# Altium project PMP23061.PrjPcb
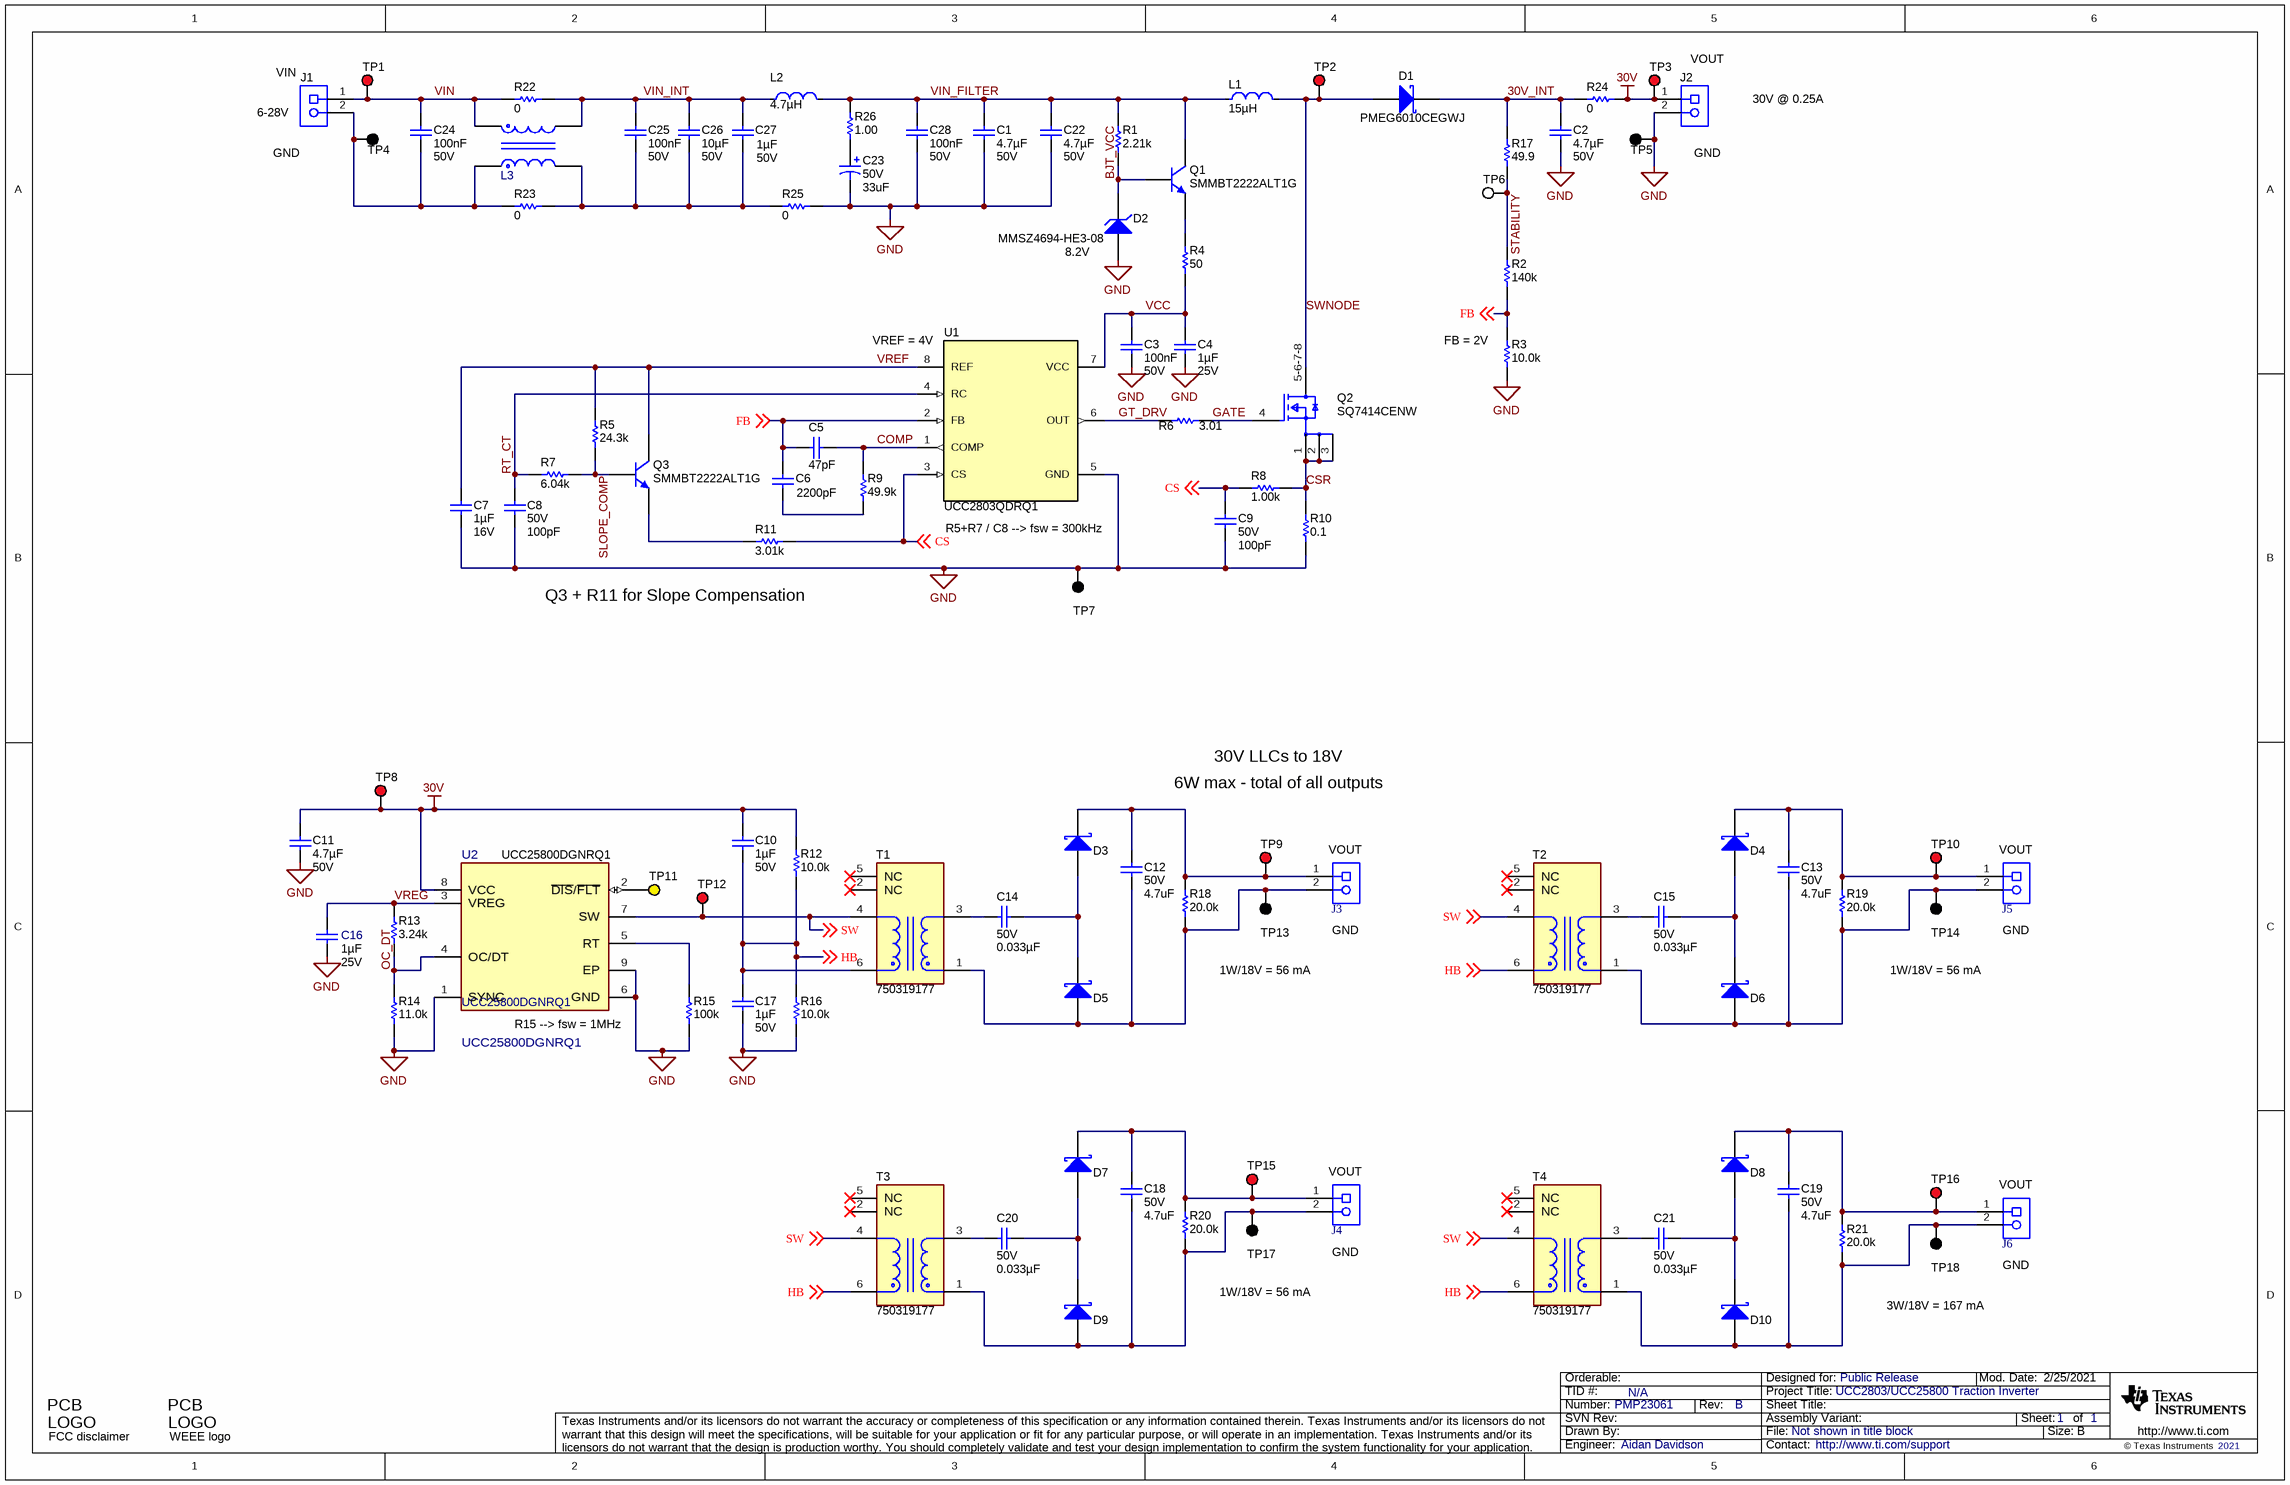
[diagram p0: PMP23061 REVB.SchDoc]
TID: N/A; TechSupport: http://www.ti.com/support; SCH_Rev: B; PRJ_Title: UCC2803/UCC25800 Traction Inverter; PRJ_Number: PMP23061; PRJ_Engineer: Aidan Davidson; PRJ_Customer: Public Release; PCB_Rev: B; PCB_Layout: Aidan Davidson; CopyrightYear: 2021
1 sheet, 102 parts. Net scope: global (net labels, ports and power ports of the same name join across sheets).
Board file: PMP23061 REVB.PcbDoc

## Sheet PMP23061 REVB.SchDoc
size 431 x 279 mm; Date: Not shown in title block; ApprovedBy: Not shown in title block; CheckedBy: Not shown in title block; Author: Not shown in title block; CompanyName: Not shown in title block; Engineer: Not shown in title block; Organization: Not shown in title block; Address1: Not shown in title block; Address2: Not shown in title block; Address3: Not shown in title block; Address4: Not shown in title block; DocumentNumber: 1; Revision: Use project parameter SCH_Rev; SheetNumber: 1; SheetTotal: 1; PageSetup: Record=PageOptions¦CenterHorizontal=True¦CenterVertical=True¦PrintScale=1.00¦XCorrection=1.00¦YCorrection=1.00¦PrintKind=0¦BorderSize=5000000¦LeftOffset=0¦BottomOffset=0¦Orientation=2¦PaperLength=1000¦PaperWidth=1000¦Scale=100¦PaperSource=15¦PrintQuality=600¦MediaType=1¦DitherType=10¦PaperKind=Letter¦PrintScaleMode=1

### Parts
C1  ValueDisplayed: 4.7µF  VDC_V: 50V  [1206_190]  (hidden comment: CGA5L3X7R1H475K160AE)
C2  ValueDisplayed: 4.7µF  VDC_V: 50V  [1206_190]  (hidden comment: CGA5L3X7R1H475K160AE)
C3  Cap_F: 100nF  VDC_V: 50V  [0603]  (hidden comment: CGA3E2X7R1H104K080AA)
C4  Cap_F: 1µF  VDC_V: 25V  [0603]  (hidden comment: GCM188R71E105KA64D)
C5  ValueDisplayed: 47pF  [0402]  (hidden comment: CGA2B2C0G1H470J050BA)
C6  ValueDisplayed: 2200pF  [0402]  (hidden comment: GCM155R71H222KA37D)
C7  Cap_F: 1µF  VDC_V: 16V  [0603]  (hidden comment: GCM188R71C105MA64D)
C8  VDC_V: 50V  ValueDisplayed: 100pF  [0402]  (hidden comment: CGA2B2C0G1H101J050BA)
C9  VDC_V: 50V  ValueDisplayed: 100pF  [0402]  (hidden comment: CGA2B2C0G1H101J050BA)
C10  Cap_F: 1µF  VDC_V: 50V  [0805_HV]  (hidden comment: CGA4J3X7R1H105K125AB)
C11  ValueDisplayed: 4.7µF  VDC_V: 50V  [1206_190]  (hidden comment: CGA5L3X7R1H475K160AE)
C12  VDC_V: 50V  ValueDisplayed: 4.7uF  [1210_280]  (hidden comment: CGA6P3X7R1H475K250AB)
C13  VDC_V: 50V  ValueDisplayed: 4.7uF  [1210_280]  (hidden comment: CGA6P3X7R1H475K250AB)
C14  VDC_V: 50V  ValueDisplayed: 0.033µF  [0805_HV]  (hidden comment: CGA4J2C0G1H333J125AA)
C15  VDC_V: 50V  ValueDisplayed: 0.033µF  [0805_HV]  (hidden comment: CGA4J2C0G1H333J125AA)
C16  Cap_F: 1µF  VDC_V: 25V  [0603S]  (hidden comment: CGA3E1X7R1E105K080AC)
C17  Cap_F: 1µF  VDC_V: 50V  [0805_HV]  (hidden comment: CGA4J3X7R1H105K125AB)
C18  VDC_V: 50V  ValueDisplayed: 4.7uF  [1210_280]  (hidden comment: CGA6P3X7R1H475K250AB)
C19  VDC_V: 50V  ValueDisplayed: 4.7uF  [1210_280]  (hidden comment: CGA6P3X7R1H475K250AB)
C20  VDC_V: 50V  ValueDisplayed: 0.033µF  [0805_HV]  (hidden comment: CGA4J2C0G1H333J125AA)
C21  VDC_V: 50V  ValueDisplayed: 0.033µF  [0805_HV]  (hidden comment: CGA4J2C0G1H333J125AA)
C22  ValueDisplayed: 4.7µF  VDC_V: 50V  [1206_190]  (hidden comment: CGA5L3X7R1H475K160AE)
C23  VDC_V: 50V  ValueDisplayed: 33uF  [HXA_F80]  (hidden comment: HHXA500ARA330MF80G)
C24  Cap_F: 100nF  VDC_V: 50V  [0603]  (hidden comment: CGA3E2X7R1H104K080AA)
C25  Cap_F: 100nF  VDC_V: 50V  [0603]  (hidden comment: CGA3E2X7R1H104K080AA)
C26  ValueDisplayed: 10µF  VDC_V: 50V  [1206]  (hidden comment: CGA5L1X7R1H106K160AE)
C27  VDC_V: 50V  ValueDisplayed: 1µF  [1206_180]  (hidden comment: UMK316B7105KLHT)
C28  Cap_F: 100nF  VDC_V: 50V  [0603]  (hidden comment: CGA3E2X7R1H104K080AA)
D1  PMEG6010CEGWJ  [SOD-123]
D2  MMSZ4694-HE3-08  value 8.2V  [SOD-123]
D3  PMEG6010CEGWJ  [SOD-123]  (value not drawn)
D4  PMEG6010CEGWJ  [SOD-123]  (value not drawn)
D5  PMEG6010CEGWJ  [SOD-123]  (value not drawn)
D6  PMEG6010CEGWJ  [SOD-123]  (value not drawn)
D7  PMEG6010CEGWJ  [SOD-123]  (value not drawn)
D8  PMEG6010CEGWJ  [SOD-123]  (value not drawn)
D9  PMEG6010CEGWJ  [SOD-123]  (value not drawn)
D10  PMEG6010CEGWJ  [SOD-123]  (value not drawn)
J1  ED555/2DS  [TERM_BLK_ED555-2DS]  (value not drawn)
J2  ED555/2DS  [TERM_BLK_ED555-2DS]  (value not drawn)
J3  691213710002  [Wurth_691213710002]  (value not drawn)
J4  691213710002  [Wurth_691213710002]  (value not drawn)
J5  691213710002  [Wurth_691213710002]  (value not drawn)
J6  691213710002  [Wurth_691213710002]  (value not drawn)
L1  Ind_H: 15µH  [FP-SPM7054VT- 470M-D_STM_7MM5_7MM0-0]  (hidden comment: SPM7054VT- 150M-D)
L2  Ind_H: 4.7µH  [FP-ETQP3M4R7KVN_SMT_6MM4_6MM0-MFG]  (hidden comment: ETQP3M4R7KVN)
L3  DLW5BTH142TQ2L  [FP-DLW5BTH142TQ2L_SMT_5MM0_5MM0-MFG]  (value not drawn)
Logo1  FCC disclaimer  [FCC_disclaimer]  (no BOM)
Logo2  WEEE logo  [WEEE_Minimum]  (no BOM)
Q1  SMMBT2222ALT1G  [SOT-23]
Q2  SQ7414CENW  [FP-SQ7414CENW_PowerPAK_1212-8W-SINGLE-MFG]
Q3  SMMBT2222ALT1G  [SOT-23]
R1  ValueDisplayed: 2.21k  [1206]  (hidden comment: CRCW12062K21FKEA)
R2  ValueDisplayed: 140k  [0603]  (hidden comment: CRCW0603140KFKEA)
R3  ValueDisplayed: 10.0k  [0402]  (hidden comment: CRCW040210K0FKED)
R4  ValueDisplayed: 50  [0603]  (hidden comment: CRCW060350R0FKEA)
R5  ValueDisplayed: 24.3k  [0402]  (hidden comment: CRCW040224K3FKED)
R6  ValueDisplayed: 3.01  [0603]  (hidden comment: CRCW06033R01FKEA)
R7  ValueDisplayed: 6.04k  [0402]  (hidden comment: CRCW04026K04FKED)
R8  ValueDisplayed: 1.00k  [0402]  (hidden comment: CRCW04021K00FKED)
R9  ValueDisplayed: 49.9k  [0402]  (hidden comment: CRCW040249K9FKED)
R10  ValueDisplayed: 0.1  [2512]  (hidden comment: ERJ-L1WKF10CU)
R11  ValueDisplayed: 3.01k  [0402]  (hidden comment: CRCW04023K01FKED)
R12  ValueDisplayed: 10.0k  [0603]  (hidden comment: CRCW060310K0FKEA)
R13  ValueDisplayed: 3.24k  [0402]  (hidden comment: CRCW04023K24FKED)
R14  ValueDisplayed: 11.0k  [0402]  (hidden comment: CRCW040211K0FKED)
R15  ValueDisplayed: 100k  [0402]  (hidden comment: CRCW0402100KFKED)
R16  ValueDisplayed: 10.0k  [0603]  (hidden comment: CRCW060310K0FKEA)
R17  ValueDisplayed: 49.9  [0603]  (hidden comment: CRCW060349R9FKEA)
R18  ValueDisplayed: 20.0k  [1206]  (hidden comment: CRCW120620K0FKEA)
R19  ValueDisplayed: 20.0k  [1206]  (hidden comment: CRCW120620K0FKEA)
R20  ValueDisplayed: 20.0k  [1206]  (hidden comment: CRCW120620K0FKEA)
R21  ValueDisplayed: 20.0k  [1206]  (hidden comment: CRCW120620K0FKEA)
R22  ValueDisplayed: 0  [1206]  (hidden comment: CRCW12060000Z0EA)
R23  ValueDisplayed: 0  [1206]  (hidden comment: CRCW12060000Z0EA)
R24  ValueDisplayed: 0  [1206]  (hidden comment: CRCW12060000Z0EA)
R25  ValueDisplayed: 0  [1206]  (hidden comment: CRCW12060000Z0EA)
R26  ValueDisplayed: 1.00  [0603]  (hidden comment: CRCW06031R00FKEA)
T1  750319177  [FP-750319177_SMT_XFRMR_13MM36_10MM16-MFG]
T2  750319177  [FP-750319177_SMT_XFRMR_13MM36_10MM16-MFG]
T3  750319177  [FP-750319177_SMT_XFRMR_13MM36_10MM16-MFG]
T4  750319177  [FP-750319177_SMT_XFRMR_13MM36_10MM16-MFG]
TP1  5010  [Keystone5010]  (value not drawn)
TP2  5010  [Keystone5010]  (value not drawn)
TP3  5010  [Keystone5010]  (value not drawn)
TP4  5011  [Keystone5011]  (value not drawn)
TP5  5011  [Keystone5011]  (value not drawn)
TP6  5012  [Keystone5012]  (value not drawn)
TP7  5011  [Keystone5011]  (value not drawn)
TP8  5010  [Keystone5010]  (value not drawn)
TP9  5010  [Keystone5010]  (value not drawn)
TP10  5010  [Keystone5010]  (value not drawn)
TP11  5014  [Keystone5014]  (value not drawn)
TP12  5010  [Keystone5010]  (value not drawn)
TP13  5011  [Keystone5011]  (value not drawn)
TP14  5011  [Keystone5011]  (value not drawn)
TP15  5010  [Keystone5010]  (value not drawn)
TP16  5010  [Keystone5010]  (value not drawn)
TP17  5011  [Keystone5011]  (value not drawn)
TP18  5011  [Keystone5011]  (value not drawn)
U1  UCC2803QDRQ1  [D0008A_N]
U2  UCC25800DGNRQ1  [DGN0008G-MFG]

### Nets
30V: C10.1 C11.2 J2.1 R12.2 R24.2 TP3.1 TP8.1 U2.8(VCC)
GND: C1.2 C2.2 C3.2 C4.2 C7.2 C8.2 C9.2 C11.1 C16.2 C17.2 C22.2 C23.2(-) C28.2 D2.2(A) J2.2 R3.1 R10.1 R14.1 R15.1 R16.1 R25.2 TP5.1 TP7.1 U1.5(GND) U2.1(SYNC) U2.6(GND) U2.9(EP)
30V_INT: C2.1 D1.1(K) R17.2 R24.1
BJT_VCC: D2.1(K) Q1.1(B) R1.1
COMP: C5.1 R9.2 U1.1(COMP)
CS: C9.1 R8.1 R11.2 U1.3(CS) ; off-sheet CS
CSR: Q2.1(S) Q2.2(S) Q2.3(S) R8.2 R10.2
FB: C5.2 C6.1 R2.1 R3.2 U1.2(FB) ; off-sheet FB
GATE: Q2.4(G) R6.2
GT_DRV: R6.1 U1.6(OUT)
HB: C10.2 C17.1 R12.1 R16.2 T1.6 T2.6 T3.6 T4.6 ; off-sheet HB
OC_DT: R13.1 R14.2 U2.4(OC/DT)
RT_CT: C8.1 R7.2 U1.4(RC)
SLOPE_COMP: Q3.1(B) R5.1 R7.1
STABILITY: R2.2 R17.1 TP6.1
SW: T1.4 T2.4 T3.4 T4.4 TP12.1 U2.7(SW) ; off-sheet SW
SWNODE: D1.2(A) L1.2 Q2.5-6-7-8(D) TP2.1
VCC: C3.1 C4.1 R4.1 U1.7(VCC)
VIN: C24.1 J1.1 L3.1 R22.1 TP1.1
VIN_FILTER: C1.1 C22.1 C28.1 L1.1 L2.2 Q1.3(C) R1.2 R26.2
VIN_INT: C25.1 C26.1 C27.1 L2.1 L3.2 R22.2
VREF: C7.1 Q3.3(C) R5.2 U1.8(REF)
VREG: C16.1 R13.2 U2.3(VREG)
NetC6_2: C6.2 R9.1
NetC12_1: C12.1 D3.1(K) J3.1 R18.2 TP9.1
NetC12_2: C12.2 D5.2(A) J3.2 R18.1 T1.1 TP13.1
NetC13_1: C13.1 D4.1(K) J5.1 R19.2 TP10.1
NetC13_2: C13.2 D6.2(A) J5.2 R19.1 T2.1 TP14.1
NetC14_1: C14.1 T1.3
NetC14_2: C14.2 D3.2(A) D5.1(K)
NetC15_1: C15.1 T2.3
NetC15_2: C15.2 D4.2(A) D6.1(K)
NetC18_1: C18.1 D7.1(K) J4.1 R20.2 TP15.1
NetC18_2: C18.2 D9.2(A) J4.2 R20.1 T3.1 TP17.1
NetC19_1: C19.1 D8.1(K) J6.1 R21.2 TP16.1
NetC19_2: C19.2 D10.2(A) J6.2 R21.1 T4.1 TP18.1
NetC20_1: C20.1 T3.3
NetC20_2: C20.2 D7.2(A) D9.1(K)
NetC21_1: C21.1 T4.3
NetC21_2: C21.2 D8.2(A) D10.1(K)
NetC23_1: C23.1(+) R26.1
NetC24_2: C24.2 J1.2 L3.4 R23.1 TP4.1
NetC25_2: C25.2 C26.2 C27.2 L3.3 R23.2 R25.1
NetQ1_2: Q1.2(E) R4.2
NetQ3_2: Q3.2(E) R11.1
NetR15_2: R15.2 U2.5(RT)
NetTP11_1: TP11.1 U2.2(~{DIS}/~{FLT})

Not connected (* = marked no-connect by the designer): T1 2(NC)* 5(NC)*; T2 2(NC)* 5(NC)*; T3 2(NC)* 5(NC)*; T4 2(NC)* 5(NC)*

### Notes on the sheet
- (near J1) VIN
- VOUT
- 30V @ 0.25A
- (near J1) 6-28V
- GND
- (near U1) VREF = 4V
- (near R3) FB = 2V
- R5+R7 / C8 --> fsw = 300kHz
- (near R11) Q3 + R11 for Slope Compensation
- 30V LLCs to 18V
- 6W max - total of all outputs
- (near J3) VOUT
- (near J5) VOUT
- 1W/18V = 56 mA
- (near J3) GND
- (near J5) GND
- (near U2) R15 --> fsw = 1MHz
- (near J4) VOUT
- (near J6) VOUT
- (near J4) GND
- 3W/18V = 167 mA
- (near J6) GND

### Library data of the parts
C1 C2 C11 C22 = CMP-0085349-1: CAP, CERM, 4.7 µF, 50 V,+/- 10%, X7R, AEC-Q200 Grade 1, 1206; Manufacturer: TDK; Cap_Case: 1206; AEC Category: Q200; SizeY_mm: 1.6; TaMin_C: -55°C; TaMax_C: 125°C; U/M: EA; AEC Qualified: Y; SizeAreaWB_mm2: 10.92; AEC Grade: 1; SizeZ_mm: 1.9; SizeArea_mm2: 5.12; Value: 4.7uF; Polarized: N; SizeX_mm: 3.2
C3 C24 C25 C28 = CMP-0007078-4: CAP, CERM, 0.1 uF, 50 V, +/- 10%, X7R, AEC-Q200 Grade 1, 0603; Manufacturer: TDK; TaMin_C: -55°C; ESR_ohm: 0.0296; Polarized: N; SizeAreaWB_mm2: 4.68; Value1: 0.0296 ohm; U/M: EA; Value: 0.1uF; TaMax_C: 125°C; SizeZ_mm: 1; SizeX_mm: 1.6; SizeY_mm: 0.8; SizeArea_mm2: 1.28; AEC Qualified: Y; IRMS_A: 971.99mA; AEC Category: Q200
C4 = CMP-0007139-4: CAP, CERM, 1 uF, 25 V, +/- 10%, X7R, AEC-Q200 Grade 1, 0603; Manufacturer: MuRata; TaMin_C: -55°C; Polarized: N; SizeAreaWB_mm2: 4.68; Value1: Unknown; U/M: EA; Value: 1uF; TaMax_C: 125°C; SizeZ_mm: 1; SizeX_mm: 1.6; SizeY_mm: 0.8; SizeArea_mm2: 1.28; AEC Qualified: Y; AEC Category: Q200
C5 = CMP-0860832-1: CAP, CERM, 47 pF, 50 V,+/- 5%, C0G/NP0, AEC-Q200 Grade 1, 0402; Manufacturer: TDK; SizeZ_mm: 0.6; SizeAreaWB_mm2: 3; AEC Qualified: Y; AEC Category: Q200; TaMax_C: 125°C; SizeY_mm: 0.5; AEC Grade: 1; Value2: 50V; TaMin_C: -55°C; Polarized: N; Value: 47pF; U/M: EA
C6 = CMP-0006357-2: CAP, CERM, 2200 pF, 50 V, +/- 10%, X7R, AEC-Q200 Grade 1, 0402; Manufacturer: MuRata; TaMin_C: -55°C; Polarized: N; SizeAreaWB_mm2: 3; Value1: Unknown; U/M: EA; Value: 2200pF; TaMax_C: 125°C; SizeZ_mm: 0.6; SizeX_mm: 1; SizeY_mm: 0.5; Value2: 50V; AEC Qualified: Y; Cap_F: 2.2nF; AEC Category: Q200
C7 = CMP-0007137-5: CAP, CERM, 1 uF, 16 V, +/- 20%, X7R, AEC-Q200 Grade 1, 0603; Manufacturer: MuRata; TaMin_C: -55°C; Polarized: N; SizeAreaWB_mm2: 4.68; Value1: Unknown; U/M: EA; Value: 1uF; TaMax_C: 125°C; SizeZ_mm: 1; SizeX_mm: 1.6; SizeY_mm: 0.8; SizeArea_mm2: 1.28; AEC Qualified: Y; AEC Category: Q200
C8 C9 = CMP-0006308-2: CAP, CERM, 100 pF, 50 V, +/- 5%, C0G/NP0, AEC-Q200 Grade 1, 0402; Manufacturer: TDK; TaMin_C: -55°C; Polarized: N; SizeAreaWB_mm2: 3; Value1: Unknown; U/M: EA; Value: 100pF; TaMax_C: 125°C; SizeZ_mm: 0.6; SizeX_mm: 1; SizeY_mm: 0.5; AEC Qualified: Y; AEC Category: Q200
C10 C17 = CMP-0007976-2: CAP, CERM, 1 uF, 50 V, +/- 10%, X7R, AEC-Q200 Grade 1, 0805; Manufacturer: TDK; TaMin_C: -55°C; ESR_ohm: 8.782m; Polarized: N; SizeAreaWB_mm2: 6.75; Value1: 0.008782 ohm; U/M: EA; Value: 1uF; TaMax_C: 125°C; SizeZ_mm: 1.45; SizeX_mm: 2; SizeY_mm: 1.25; Cap_Case: 0805; SizeArea_mm2: 2.5; AEC Qualified: Y; IRMS_A: 2.20488A; AEC Grade: 1; AEC Category: Q200
C12 C13 C18 C19 = CMP-0009162-2: CAP, CERM, 4.7 uF, 50 V, +/- 10%, X7R, AEC-Q200 Grade 1, 1210; Manufacturer: TDK; TaMin_C: -55°C; ESR_ohm: 3.166m; Polarized: N; SizeAreaWB_mm2: 14.7; Value1: 0.003166 ohm; U/M: EA; Value: 4.7uF; TaMax_C: 125°C; SizeZ_mm: 2.8; SizeX_mm: 3.2; SizeY_mm: 2.5; SizeArea_mm2: 8; AEC Qualified: Y; Cap_F: 4.7µF; IRMS_A: 4.1331A; AEC Grade: 1; AEC Category: Q200
C14 C15 C20 C21 = CMP-0080742-1: CAP, CERM, 0.033 µF, 50 V,+/- 5%, C0G/NP0, AEC-Q200 Grade 1, 0805; Manufacturer: TDK; Cap_F: 33nF; SizeAreaWB_mm2: 6.75; SizeArea_mm2: 2.5; AEC Qualified: Y; AEC Category: Q200; Value: 0.033uF; TaMax_C: 125°C; SizeZ_mm: 1.45; AEC Grade: 1; Polarized: N; TaMin_C: -55°C; SizeY_mm: 1.25; U/M: EA; SizeX_mm: 2; Cap_Case: 0805
C16 = CMP-0076705-3: CAP, CERM, 1 µF, 25 V,+/- 10%, X7R, AEC-Q200 Grade 1, 0603; Manufacturer: TDK; SizeAreaWB_mm2: 4.68; SizeArea_mm2: 1.28; AEC Qualified: Y; AEC Category: Q200; Value: 1uF; TaMax_C: 125°C; SizeZ_mm: 1.0; AEC Grade: 1; Polarized: N; TaMin_C: -55°C; SizeY_mm: 0.8; U/M: EA; SizeX_mm: 1.6; Cap_Case: 1.6x0.8x0.8mm
C23 = CMP-0012264-3: CAP, Aluminum Polymer, 33 uF, 50 V, +/- 20%, 0.04 ohm, AEC-Q200 Grade 1, D6.3xL7.7mm SMD; Manufacturer: Chemi-Con; TaMin_C: -55°C; ESR_ohm: 0.04; Polarized: Y; SizeAreaWB_mm2: 79.12; Value: 33uF; TaMax_C: 125°C; SizeZ_mm: 8; SizeX_mm: 7.2; SizeY_mm: 6.6; Cap_Case: 6.3x7.7mm; SizeArea_mm2: 47.52; CompType: Capacitor; Cap_F: 33µF; IRMS_A: 1.1A; AEC Grade: 1; AEC Category: Q200
C26 = CMP-0860898-1: CAP, CERM, 10 µF, 50 V,+/- 10%, X7R, AEC-Q200 Grade 1, 1206; Manufacturer: TDK; SizeY_mm: 1.6; AEC Category: Q200; U/M: EA; Polarized: N; TaMin_C: -55°C; TaMax_C: 125°C; SizeX_mm: 3.2; AEC Qualified: Y; SizeZ_mm: 1.35; Value: 10uF; SizeArea_mm2: 5.12; SizeAreaWB_mm2: 10.92; AEC Grade: 1
C27 = CMP-0080106-1: CAP, CERM, 1 µF, 50 V,+/- 10%, X7R, AEC-Q200 Grade 1, 1206; Manufacturer: Taiyo Yuden; SizeAreaWB_mm2: 10.92; SizeArea_mm2: 5.12; AEC Qualified: Y; AEC Category: Q200; Value: 1uF; TaMax_C: 125°C; SizeZ_mm: 1.8; AEC Grade: 1; Polarized: N; TaMin_C: -55°C; SizeY_mm: 1.6; U/M: EA; SizeX_mm: 3.2; Cap_Case: 1206
D1 D3-D10 = CMP-0079239-2: Diode, Schottky, 60 V, 1 A, AEC-Q101, SOD-123; Manufacturer: Nexperia; SizeY_mm: 1.7; AEC Qualified: Y; SizeArea_mm2: 6.545; Vf_V: 660mV; Value: 60V; Value1: 1A; AEC Category: Q101; TJmax_C: 150°C; SizeX_mm: 3.85; SizeZ_mm: 1.35; SizeAreaWB_mm2: 13.095; Value2: 0.66V
D2 = CMP-0077567-3: Diode, Zener, 8.2 V, 500 mW, AEC-Q101, SOD-123; Manufacturer: Vishay-Semiconductor; RJA_CperW: 340; SizeArea_mm2: 6.545; AEC Qualified: Y; SizeY_mm: 1.7; Power_W: 500mW; Value1: 0.5W; SizeZ_mm: 1.35; SizeX_mm: 3.85; SizeAreaWB_mm2: 13.095; AEC Category: Q101
J1 J2 = CMP-0074913-1: Terminal Block, 3.5mm Pitch, 2x1, TH; Manufacturer: On-Shore Technology; Cert_VDE: Y; CNHeader: False; Current_A: 6A; Green_Lifecycle: Active; Shrouded: N; Gender: Female; Green_REACh: Passed; Voltage_V: 150V; Row_Count: 1; Pitch_mm: 3.5; ContactFinish: Brass; CT: True
J3-J6 = CMP-0054823-2: Terminal Block, 2x1, Brass, TH; Manufacturer: Wurth Elektronik; CNHeader: FALSE; Green_Lifecycle: Active; Gender: Female; Green_REACh: Passed; Row_Count: 1; Pitch_mm: 5; CT: TRUE
L1 = CMP-0088010-1: SMD Power Inductor; Manufacturer: TDK; Symbol Name: SYM-SPM7054VT- 150M-D; AEC Grade: Grade 0; DCR_ohm: 0.0548; AEC Qualified: Yes; SizeZ_mm: 5.4mm; Isat: 5.0A
L2 = CMP-0086492-1: 4.7µH Shielded  Inductor 5.6A 31.9 mOhm Max 2-SMD, J-Lead; Manufacturer: Panasonic; SizeZ_mm: 3mm; AEC Grade: Grade 0; AEC Qualified: Yes; Material: Metal composite; Irms: 4.6A; Isat: 9.8A; Symbol Name: SYM-ETQP3M4R7KVN; DCR_ohm: 0.0319
L3 = CMP-0087211-1: Wire Wound Chip Common Mode Choke Coil; Manufacturer: Murata; AEC Grade: Grade 1; SizeZ_mm: 2.5mm; DCR_ohm: 0.056; AEC Qualified: Yes
Logo1 = CMP-0074847-1: FCC_disclaimer; Library Reference: Logo
Logo2 = CMP-0074769-1
Q1 Q3 = CMP-0750169-1: Transistor, NPN, 40 V, 0.6 A, AEC-Q101, SOT-23; Manufacturer: ON Semiconductor; Vceo_V: 40V; SizeX_mm: 2.5; NPN: 1; IcRated_A: 600mA; SizeZ_mm: 1.1; SizeY_mm: 3; Value: 40 V; AEC Qualified: Y; CompType: BJT; TaMax_C: 150°C; SizeArea_mm2: 7.5; PNP: 0; Value1: 0.6 A; AEC Category: Q101; TaMin_C: -55°C; Vcesat1_V: 300mV; SizeAreaWB_mm2: 14
Q2 = CMP-0092401-1: N-Channel 18A (Tc) 62W (Tc) Surface Mount PowerPAK® 1212-8W; Manufacturer: Vishay; Number Of Channels: 1; Input Capacitace At Vds: 1275pF @ 30V; AEC Grade: Grade 0; SizeZ_mm: 1.17mm; QgTyp_nC: 19nC @ 10V; Standoff Height: 0mm; Rthja Max: 81°C/W; Threshold Vgs Min: 1.5V; Rdson45_ohm: 16m; VdsMax_V: 1.2V; Pulse Drain Current: 72A; ChMode: False; Drain To Source Breakdown Voltage: 60V; Turn Off Delay Time: 22ns; Vgs_V: 20V; Transconductance: 50S; Typ Forward Diode Voltage: 0.8V; Turn On Delay Time: 8ns; TJmax_C: +175°C; AEC Qualified: Yes; Threshold Vgs Max: 2.5V
R1 = CMP-0016848-3: RES, 2.21 k, 1%, 0.25 W, AEC-Q200 Grade 0, 1206; Manufacturer: Vishay-Dale; Power_W: 250mW; TempCo: 100 ppm/C; Value_Code: 2k21; Value: 2.21k; EIA_Code: E96; SizeX_mm: 3.2; SizeY_mm: 1.6; SizeZ_mm: 1.35; Value2: 0.25W; SizeArea_mm2: 5.12; AEC Qualified: Y; VDC_V: 200V; AEC Category: Q200; AEC Grade: 0
R2 = CMP-0022048-4: RES, 140 k, 1%, 0.1 W, AEC-Q200 Grade 0, 0603; Manufacturer: Vishay-Dale; Power_W: 100mW; TempCo: 100 ppm/C; Value: 140k; EIA_Code: E96; SizeX_mm: 1.6; SizeY_mm: 0.8; SizeZ_mm: 1; Value2: 0.1W; SizeArea_mm2: 1.28; AEC Qualified: Y; VDC_V: 75V; AEC Category: Q200; AEC Grade: 0
R3 = CMP-0025958-3: RES, 10.0 k, 1%, 0.063 W, AEC-Q200 Grade 0, 0402; Manufacturer: Vishay-Dale; Power_W: 63mW; TempCo: 100 ppm/C; Value_Code: 10k0; Value: 10.0k; EIA_Code: E96; Res_ohm: 10k; SizeX_mm: 1; SizeY_mm: 0.5; SizeZ_mm: 0.6; Value2: 0.063W; AEC Qualified: Y; VDC_V: 50V; AEC Category: Q200; AEC Grade: 0
R4 = CMP-0022479-4: RES, 50, 1%, 0.1 W, AEC-Q200 Grade 0, 0603; Manufacturer: Vishay-Dale; Power_W: 100mW; TempCo: 100 ppm/C; Value_Code: 50R0; Value: 50; SizeX_mm: 1.6; SizeY_mm: 0.8; SizeZ_mm: 1; Value2: 0.1W; SizeArea_mm2: 1.28; AEC Qualified: Y; VDC_V: 75V; AEC Category: Q200; AEC Grade: 0
R5 = CMP-0026195-2: RES, 24.3 k, 1%, 0.063 W, AEC-Q200 Grade 0, 0402; Manufacturer: Vishay-Dale; Power_W: 63mW; TempCo: 100 ppm/C; Value_Code: 24k3; Value: 24.3k; EIA_Code: E96; SizeX_mm: 1; SizeY_mm: 0.5; SizeZ_mm: 0.6; Value2: 0.063W; AEC Qualified: Y; VDC_V: 50V; AEC Category: Q200; AEC Grade: 0
R6 = CMP-0022396-4: RES, 3.01, 1%, 0.1 W, AEC-Q200 Grade 0, 0603; Manufacturer: Vishay-Dale; Power_W: 100mW; TempCo: 100 ppm/C; Value_Code: 3R01; Value: 3.01; EIA_Code: E96; SizeX_mm: 1.6; SizeY_mm: 0.8; SizeZ_mm: 1; Value2: 0.1W; SizeArea_mm2: 1.28; AEC Qualified: Y; VDC_V: 75V; AEC Category: Q200; AEC Grade: 0
R7 = CMP-0026512-2: RES, 6.04 k, 1%, 0.063 W, AEC-Q200 Grade 0, 0402; Manufacturer: Vishay-Dale; Power_W: 63mW; TempCo: 100 ppm/C; Value_Code: 6k04; Value: 6.04k; EIA_Code: E96; SizeX_mm: 1; SizeY_mm: 0.5; SizeZ_mm: 0.6; Value2: 0.063W; AEC Qualified: Y; VDC_V: 50V; AEC Category: Q200; AEC Grade: 0
R8 = CMP-0026071-3: RES, 1.00 k, 1%, 0.063 W, AEC-Q200 Grade 0, 0402; Manufacturer: Vishay-Dale; Power_W: 63mW; TempCo: 100 ppm/C; Value_Code: 1k00; Value: 1.00k; EIA_Code: E96; Res_ohm: 1k; SizeX_mm: 1; SizeY_mm: 0.5; SizeZ_mm: 0.6; Value2: 0.063W; AEC Qualified: Y; VDC_V: 50V; AEC Category: Q200; AEC Grade: 0
R9 = CMP-0026403-2: RES, 49.9 k, 1%, 0.063 W, AEC-Q200 Grade 0, 0402; Manufacturer: Vishay-Dale; Power_W: 63mW; TempCo: 100 ppm/C; Value_Code: 49k9; Value: 49.9k; EIA_Code: E96; SizeX_mm: 1; SizeY_mm: 0.5; SizeZ_mm: 0.6; Value2: 0.063W; AEC Qualified: Y; VDC_V: 50V; AEC Category: Q200; AEC Grade: 0
R10 = CMP-0015806-2: RES, 0.1, 1%, 1 W, 2512; Manufacturer: Panasonic; Power_W: 1W; TempCo: 100 ppm/C; Value_Code: R100; U/M: EA; Value: 0.1; EIA_Code: E96; SizeX_mm: 6.3; SizeY_mm: 3.2; SizeZ_mm: 0.71; SizeArea_mm2: 20.16; VDC_V: 0V; AEC Category: Q200
R11 = CMP-0026329-2: RES, 3.01 k, 1%, 0.063 W, AEC-Q200 Grade 0, 0402; Manufacturer: Vishay-Dale; Power_W: 63mW; TempCo: 100 ppm/C; Value_Code: 3k01; Value: 3.01k; EIA_Code: E96; SizeX_mm: 1; SizeY_mm: 0.5; SizeZ_mm: 0.6; Value2: 0.063W; AEC Qualified: Y; VDC_V: 50V; AEC Category: Q200; AEC Grade: 0
R12 R16 = CMP-0021998-4: RES, 10.0 k, 1%, 0.1 W, AEC-Q200 Grade 0, 0603; Manufacturer: Vishay-Dale; Power_W: 100mW; TempCo: 100 ppm/C; Value_Code: 10k0; Value: 10.0k; EIA_Code: E96; Res_ohm: 10k; SizeX_mm: 1.6; SizeY_mm: 0.8; SizeZ_mm: 1; Value2: 0.1W; SizeArea_mm2: 1.28; AEC Qualified: Y; VDC_V: 75V; AEC Category: Q200; AEC Grade: 0
R13 = CMP-0026332-2: RES, 3.24 k, 1%, 0.063 W, AEC-Q200 Grade 0, 0402; Manufacturer: Vishay-Dale; Power_W: 63mW; TempCo: 100 ppm/C; Value_Code: 3k24; Value: 3.24k; EIA_Code: E96; SizeX_mm: 1; SizeY_mm: 0.5; SizeZ_mm: 0.6; Value2: 0.063W; AEC Qualified: Y; VDC_V: 50V; AEC Category: Q200; AEC Grade: 0
R14 = CMP-0025975-3: RES, 11.0 k, 1%, 0.063 W, AEC-Q200 Grade 0, 0402; Manufacturer: Vishay-Dale; Power_W: 63mW; TempCo: 100 ppm/C; Value_Code: 11k0; Value: 11.0k; EIA_Code: E96; Res_ohm: 11k; SizeX_mm: 1; SizeY_mm: 0.5; SizeZ_mm: 0.6; Value2: 0.063W; AEC Qualified: Y; VDC_V: 50V; AEC Category: Q200; AEC Grade: 0
R15 = CMP-0025950-3: RES, 100 k, 1%, 0.063 W, AEC-Q200 Grade 0, 0402; Manufacturer: Vishay-Dale; Power_W: 63mW; TempCo: 100 ppm/C; Value: 100k; EIA_Code: E96; SizeX_mm: 1; SizeY_mm: 0.5; SizeZ_mm: 0.6; Value2: 0.063W; AEC Qualified: Y; VDC_V: 50V; AEC Category: Q200; AEC Grade: 0
R17 = CMP-0022448-4: RES, 49.9, 1%, 0.1 W, AEC-Q200 Grade 0, 0603; Manufacturer: Vishay-Dale; Power_W: 100mW; TempCo: 100 ppm/C; Value_Code: 49R9; Value: 49.9; EIA_Code: E96; SizeX_mm: 1.6; SizeY_mm: 0.8; SizeZ_mm: 1; Value2: 0.1W; SizeArea_mm2: 1.28; AEC Qualified: Y; VDC_V: 75V; AEC Category: Q200; AEC Grade: 0
R18-R21 = CMP-0016779-3: RES, 20.0 k, 1%, 0.25 W, AEC-Q200 Grade 0, 1206; Manufacturer: Vishay-Dale; Power_W: 250mW; TempCo: 100 ppm/C; Value_Code: 20k0; Value: 20.0k; EIA_Code: E96; Res_ohm: 20k; SizeX_mm: 3.2; SizeY_mm: 1.6; SizeZ_mm: 1.35; Value2: 0.25W; SizeArea_mm2: 5.12; AEC Qualified: Y; VDC_V: 200V; AEC Category: Q200; AEC Grade: 0
R22-R25 = CMP-0018573-3: RES, 0, 5%, 0.25 W, AEC-Q200 Grade 0, 1206; Manufacturer: Vishay-Dale; Power_W: 250mW; TempCo: 200 ppm/C; Value_Code: 0000; Value: 0; EIA_Code: E24; SizeX_mm: 3.2; SizeY_mm: 1.6; SizeZ_mm: 1.35; Value2: 0.25W; SizeArea_mm2: 5.12; AEC Qualified: Y; VDC_V: 200V; AEC Category: Q200
R26 = CMP-0022170-4: RES, 1.00, 1%, 0.1 W, AEC-Q200 Grade 0, 0603; Manufacturer: Vishay-Dale; Power_W: 100mW; TempCo: 100 ppm/C; Value_Code: 1R00; Value: 1.00; EIA_Code: E96; Res_ohm: 1; SizeX_mm: 1.6; SizeY_mm: 0.8; Value2: 0.1W; SizeArea_mm2: 1.28; AEC Qualified: Y; VDC_V: 75V; AEC Category: Q200; AEC Grade: 0
T1-T4 = CMP-0090831-1: Transformer, 1:1.67, 0.045Ohm Pri, 0.122 Sec, 16.5uH, 13.36x10.16x8.64mm; Manufacturer: Wurth Electronics; Ind_H: 16.5µH; ValueDisplayed: 1.3pF; AEC Qualified: No; Rsec1_ohm: 0.122; Frequency_Fixed: 500kHz; DCR_ohm: 45m; SizeZ_mm: 8.64mm
TP1-TP3 TP8-TP10 TP12 TP15 TP16 = CMP-0055147-1: Test Point, Multipurpose, Red, TH; Manufacturer: Keystone; CNHeader: FALSE; Green_Lifecycle: Active; Green_REACh: Passed; ContactFinish: Silver; CT: TRUE
TP4 TP5 TP7 TP13 TP14 TP17 TP18 = CMP-0055148-1: Test Point, Multipurpose, Black, TH; Manufacturer: Keystone; CNHeader: FALSE; Green_Lifecycle: Active; Green_REACh: Passed; ContactFinish: Silver; CT: TRUE
TP6 = CMP-0055149-1: Test Point, Multipurpose, White, TH; Manufacturer: Keystone; CNHeader: FALSE; Green_Lifecycle: Active; Green_REACh: Passed; ContactFinish: Silver; CT: TRUE
TP11 = CMP-0055151-1: Test Point, Multipurpose, Yellow, TH; Manufacturer: Keystone; CNHeader: FALSE; Green_Lifecycle: Active; Green_REACh: Passed; ContactFinish: Silver; CT: TRUE
U1 = CMP-0074136-1: Automotive Low-Power BiCMOS Current-Mode PWM, D0008A (SOIC-8); Alternate Manufacturer: Texas Instruments; SizeAreaWB_mm2: 56.58; U/M: EA; SizeZ_mm: 1.75; SizeX_mm: 4.9; SizeY_mm: 6.2; SizeArea_mm2: 30.38; CompType: IC
U2 = CMP-0088494-2: Open Loop LLC Transformer Driver for Isolated Bias Supplies; Manufacturer: Texas Instruments; Min Supply Voltage: 12V; SizeZ_mm: 1.1mm; Number Of Outputs: 1; Standoff Height: 0.05mm; AEC Category: Q200; Max Duty Cycle: 50%; TaMin_C: -40°C; TJmax_C: +150°C; AEC Qualified: No; Switching Frequency: 100-2000kHz; CompType: IC; Max Supply Voltage: 36V; TaMax_C: +125°C; Output Type: Other; Nominal Supply Current: 500uA

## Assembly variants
001: not fitted R22 R23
